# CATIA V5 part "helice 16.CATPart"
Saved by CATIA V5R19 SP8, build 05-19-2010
Part number: helice 16
Bounding box of the stored display mesh (mm): x -17.321 to 17.321, y -30 to 195, z -10 to 20
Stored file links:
  G:\EU_thinkMotion\CFAO_2010\MMS_groupe2\MMS_groupe2\A reprendre\splanchenault\Planchenault\helice 16.CATPart
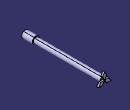
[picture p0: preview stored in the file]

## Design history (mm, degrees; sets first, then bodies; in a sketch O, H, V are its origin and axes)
Body1 (main body)
  Sketch1 on yz-plane, origin (0, 0, 0), H (0, 1, 0), V (0, 0, 1)
    line L1 (0, 0) -> (-30, 0)
    line L2 (-30, 0) -> (-30, 10)
    line L3 (-30, 10) -> (0, 10)
    point P3 (0, 10)
    line L4 (190, 7.5) -> (190, 0)
    line L5 (190, 0) -> (0, 0)
    line L6 (190, 7.5) -> (0, 7.5)
    line L7 (0, 7.5) -> (0, 10)
    length L4 = 7.5
    length L2 = 10
    length L6 = 190
    horizontal: L1 H, L3 H, L5 H, L6 H
    vertical: L2 V, L4 V
    coincidence: P3 V
    parallelism: L7 L2
  Shaft1: profile Sketch1, axis Sketch1.L1, angle 360
  Sketch2 on face of Shaft1 from Sketch1.L4, origin (0, 190, 0), H (-1, 0, 0), V (0, 0, 1)
    construction line L1 (-19.3649, -11.1803) -> (19.3649, 11.1803)
    axis line L2 (19.3649, -11.1803) -> (-19.3649, 11.1803)
    line L3 (0, 0) -> (5.7735, 10)
    point P5 (5.7735, 10)
    line L4 (5.7735, 10) -> (0, 20)
    point P6 (0, 20)
    line L5 (0, 20) -> (-5.7735, 10)
    point P7 (-5.7735, 10)
    line L6 (-5.7735, 10) -> (0, 0)
    point P8 (-17.3205, -10)
    point P9 (-5.7735, -10)
    line L7 (-5.7735, -10) -> (-17.3205, -10)
    point P10 (-11.547, 0)
    line L8 (-17.3205, -10) -> (-11.547, 0)
    point P11 (0, 0)
    line L9 (-11.547, 0) -> (0, 0)
    line L10 (0, 0) -> (-5.7735, -10)
    point P12 (17.3205, -10)
    point P13 (11.547, 0)
    line L11 (11.547, 0) -> (17.3205, -10)
    point P14 (5.7735, -10)
    line L12 (17.3205, -10) -> (5.7735, -10)
    point P15 (0, 0)
    line L13 (5.7735, -10) -> (0, 0)
    line L14 (0, 0) -> (11.547, 0)
    angle L1 V = 60
    angle L2 V = 60
    coincidence: L1 O, P6 V, O P11, O P15, P11 P15
    perpendicularity: L3 L2, L4 L1
    parallelism: L5 L3, L6 L4
    symmetry: P6 P8 L2, P5 P9 L2, L4 L7 L2, P7 P10 L2, L5 L8 L2, O P11 L2, L6 L9 L2, L3 L10 L2, P6 P12 L1, P5 P13 L1, L4 L11 L1, P7 P14 L1, L5 L12 L1, O P15 L1, L6 L13 L1, L3 L14 L1
  Pad1: profile Sketch2, direction (0, 1, 0), length 5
